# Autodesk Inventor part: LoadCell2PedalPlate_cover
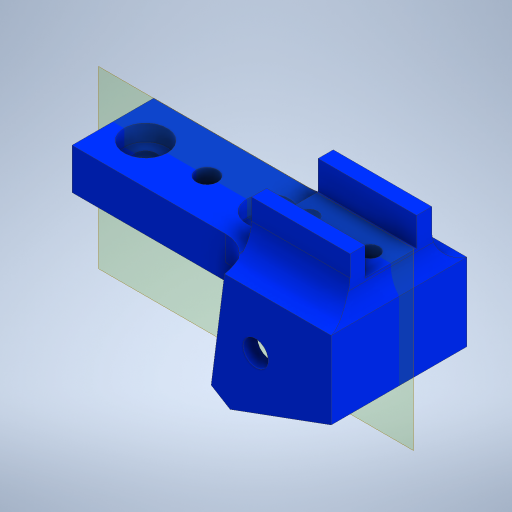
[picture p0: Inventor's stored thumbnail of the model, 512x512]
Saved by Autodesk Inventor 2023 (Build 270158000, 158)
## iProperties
Created: 2023-06
Part Number: LoadCell2PedalPlate_cover
Material: Generic
Document SubType Name: Modeling
Designer: Admin
Density: 1 g/cm^3
Appearance: Default
Author: Admin
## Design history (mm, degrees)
sketch "Sketch1"
  geometry: L1 (0, 0)-(68, 0); L2 (68, 0)-(68, -20); L3 (68, -20)-(0, -20); L4 (0, -20)-(0, 0); L5 (60, -10)-(30, -10); L6 (30, -10)-(0, -10); C1 r 2.6 at (60, -10); C2 r 2.6 at (30, -10); C3 r 2.6 at (45, -10); C4 r 2.1 at (5, -10); C5 r 2.1 at (20, -10)
  constraints: 12 end point, 5 centre point, 3 equal radius, 3 parallel, 2 horizontal, 2 midpoint, 2 point on line, 1 perpendicular
  dimensions: "d0" = 20 distance between parallel lines of L3 L1; "d2" = 30 distance of L5.start L5.end; "d3" = 8 distance from line of L5.start L2; "d5" = 5.2 diameter of C1; "d10" = 60 distance from line of L4 L5.start; "d14" = 4.2 diameter of C4; "d16" = 5 distance from line of L4 C4.centre; "d17" = 15 distance of C5.centre C4.centre
extrude "Extrusion1" new body sketch "Sketch1" distance "d6" = 10; taper "d7" = 0 deg
sketch "Sketch2"
  geometry: C1 r 2.6 at (-60, 10) reference; C2 r 5.25 at (-60, 10); C3 r 2.6 at (-30, 10) reference; C4 r 5.25 at (-30, 10); 1 further point
  constraints: 2 centre point, 2 coincident, 1 equal radius
  dimensions: "d18" = 10.5 diameter of C2
extrude "Extrusion2" cut sketch "Sketch2" distance "d19" = 4; taper "d20" = 0 deg
chamfer "Chamfer2" distance "d21" = 2; stored, may be unused: second distance "d22" = 2, angle "d23" = 45 deg
sketch "Sketch3"
  geometry: L1 (0, 20)-(-68, 20) reference; L2 (0, 0)-(0, 20) reference; L3 (-24.1, 20)-(0, 20); L4 (0, 20)-(0, 0); L5 (0, 0)-(-24.1, 0); L6 (-24.1, 0)-(-24.1, 20); C1 r 2.1 at (-5, 10); C2 r 2.1 at (-5, 10) reference; C3 r 4.1 at (-20, 10) reference; C4 r 2.1 at (-20, 10); C5 r 2.1 at (-20, 10) reference; 1 further point
  constraints: 8 end point, 4 concentric, 2 centre point, 2 parallel, 1 horizontal, 1 perpendicular, 1 point on line, 1 tangent
extrude "Extrusion3" join sketch "Sketch3" distance "d24" = 4; taper "d25" = 0 deg
sketch "Sketch4"
  geometry: L1 (-24.1, 20)-(-24.1, 0) reference; L2 (-24.1, 20)-(0, 20); L3 (0, 20)-(0, 16.3); L4 (0, 16.3)-(-24.1, 16.3); L5 (-24.1, 16.3)-(-24.1, 20); L6 (0, 0)-(-24.1, 0); L7 (-24.1, 0)-(-24.1, 3.7); L8 (-24.1, 3.7)-(0, 3.7); L9 (0, 3.7)-(0, 0); 3 further points
  constraints: 16 end point, 4 parallel, 2 collinear, 2 horizontal, 2 perpendicular, 1 point on line
  dimensions: "d26" = 12.6 distance between parallel lines of L8 L4
extrude "Extrusion4" join sketch "Sketch4" distance "d27" = 7; taper "d28" = 0 deg
fillet "Fillet1" dims "d29" = 0.6
sketch "Sketch5"
  geometry: L1 (0, 0)-(68, 0) reference; L2 (0, 4)-(68, 4); L3 (68, 0)-(68, 10) reference; L4 (22.1, 14)-(22.1, 2) reference; L5 (1.5, 0)-(1.5, 4); L6 (1.5, 4)-(0, 4); L7 (1.5, 4)-(84.489, 4); L8 (84.489, 4)-(84.489, -38.399); L9 (84.489, -38.399)-(1.5, -38.399); L10 (1.5, -38.399)-(1.5, 4); L11 (70.6, 4)-(68, 4); L12 (70.6, 4)-(-31.161, 4); L13 (84.489, -38.399)-(-31.161, 4); L14 (24.1, 8)-(24.1, 4); L15 (24.1, 8)-(-2, 8); L16 (1.5, -7.974)-(1.5, 4); L17 (24.1, 4)-(1.5, 4); L18 (24.1, 10.6)-(24.1, 21) reference; L19 (-2, -10.951)-(-2, 8); L20 (-2, -10.951)-(22.723, -20.015); L21 (1.5, -7.974)-(24.1, -16.26); L22 (22.723, -20.015)-(24.1, -16.26); C1 r 3 at (16, -4); 3 further points; 1 other entity
  constraints: 28 end point, 8 point on line, 4 collinear, 3 vertical, 2 horizontal, 2 perpendicular, 1 centre point, 1 parallel, 1 vertical alignment, 2 other
  dimensions: "d45" = 4 distance between parallel lines of L1 L2; "d60" = 6 diameter of C1; "d62" = 8 distance of point (16, 4) C1.centre; "d76" = 2.6 distance of L2.end L11.start; "d84" = 42.39919 distance between parallel lines of L7 L9; "d89" = 20.1339 deg angle of L12 L13; "d94" = 4 distance between parallel lines of L17 L15; "d102" = 1.5 distance from line of L1.start L16; "d108" = 2 distance from line of L1.start L19; "d162" = 4 distance between parallel lines of L13 L20
extrude "Extrusion5" join sketch "Sketch5" distance "d96" = 3.1; taper "d97" = 0 deg
workplane "Work Plane1"
sketch "Sketch6"
  geometry: L1 (-2, -10.951)-(22.723, -20.015) reference; L2 (0, 8)-(24.1, 8) reference; L3 (-2, 8)-(-2, -10.951) reference; L4 (24.1, 8)-(-2, 8); L5 (-2, 8)-(-2, -10.951); L6 (-2, -10.951)-(22.723, -20.015); L7 (22.723, -20.015)-(27.364, -17.2) reference; L8 (22.723, -20.015)-(27.364, -17.2); L9 (27.364, -17.2)-(24.1, 8); L10 (0, 21)-(24.1, 21) reference; L11 (0, 21)-(0, -17.744); L12 (1.5, 4)-(24.1, 4) reference; C1 r 3.1 at (16.5, -5); 2 further points
  constraints: 12 end point, 2 collinear, 1 centre point, 1 perpendicular, 1 vertical
  dimensions: "d109" = 16.5 distance from line of L11 C1.centre; "d110" = 9 distance from line of C1.centre L12; "d111" = 6.2 diameter of C1
extrude "Extrusion6" join sketch "Sketch6" distance "d112" = 3.5; taper "d113" = 0 deg
sketch "Sketch7"
  geometry: L1 (-24.1, 8)-(2, 8) reference; L2 (2, 8)-(2, -10.951); L3 (0, 0)-(0, 8) reference; L4 (0, 8)-(2, 8); L5 (0, 0)-(-1.5, 0) reference; L6 (2, 8)-(2, -10.951) reference; L7 (2, -10.951)-(-1.5, -12.234); L8 (2, -10.951)-(-22.723, -20.015) reference; L9 (-1.5, -7.974)-(-1.5, -12.234); L10 (-1.5, -7.974)-(0, -6.474); L11 (0, 8)-(0, 21) reference; L12 (0, -6.474)-(0, 8); L13 (0, 8)-(0, -6.474); 1 further point
  constraints: 14 end point, 2 collinear, 2 vertical, 1 point on line
  dimensions: "d174" = 45 deg angle of L9 L10
extrude "Extrusion7" join sketch "Sketch7" stored distance "d117" = 4; taper "d118" = 0 deg
mirror "Mirror1"
fillet "Fillet2" dims "d119" = 8
sketch "Sketch8"
  geometry: C1 r 2.1 at (-5, -10) reference; C2 r 4.1 at (-5, -10); 1 further point
  constraints: 1 centre point, 1 coincident
extrude "Extrusion8" cut sketch "Sketch8" stored distance "d171" = 10; taper "d172" = 0 deg
body "Solid1"
node "Image7"
